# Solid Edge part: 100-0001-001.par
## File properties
Title: 100-0001-00.par
Author: rtconerl
Template: ANSIMM.PAR
Last saved by: jccrumbl
Revision: 65
Application: Solid Edge
Revision: A
Teamcenter Item Type: Item
Accuracy: 0.99
TC Engineering Description: Valve Body
TC_ImportTime: 2008-07-08
PartType: -
Last Saved Version: -
Material: aluminum
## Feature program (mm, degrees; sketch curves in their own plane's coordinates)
pattern "unnamed Pattern 1"
pattern "unnamed Pattern 2"
pattern "unnamed Pattern 3"
pattern "unnamed Pattern 4"
pattern "unnamed Pattern 5"
pattern "unnamed Pattern 6"
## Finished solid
Body 1: solid body, 117 faces, 268 edges, 140 vertices.
  Faces by surface: cylinder 57, plane 30, torus 22, sphere 4, blend 2, cone 2
  Edges by curve: circle 139, line 112, intersection 17
Bounding box of the edges (mm; curved faces can reach further): 90.000 x 70.000 x 128.000, from (-45, -35, -45) to (45, 35, 83).
Cylindrical faces by radius (mm): R2 x14, R4 x22, R7.5 x1, R10 x13, R16 x2, R30 x1, R32.5 x2, R35 x2
Conical faces (half-angle, radius in mm at the cone's reference point): 45 deg R33.5 x2
Toroidal faces (ring radius, tube radius in mm): R8 r2 x12, R8 r4 x4, R20 r4 x2, R39 r4 x4
Spherical faces by radius (mm): R4 x4
Planar faces by outward normal: +x 6, +y 4, +z 5, -x 5, -y 4, -z 4, oblique 2
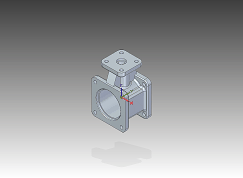
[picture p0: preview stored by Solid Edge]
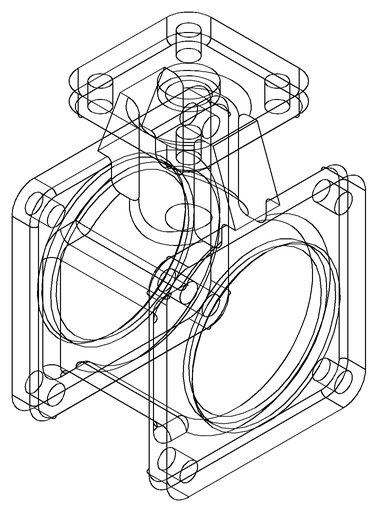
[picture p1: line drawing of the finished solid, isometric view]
